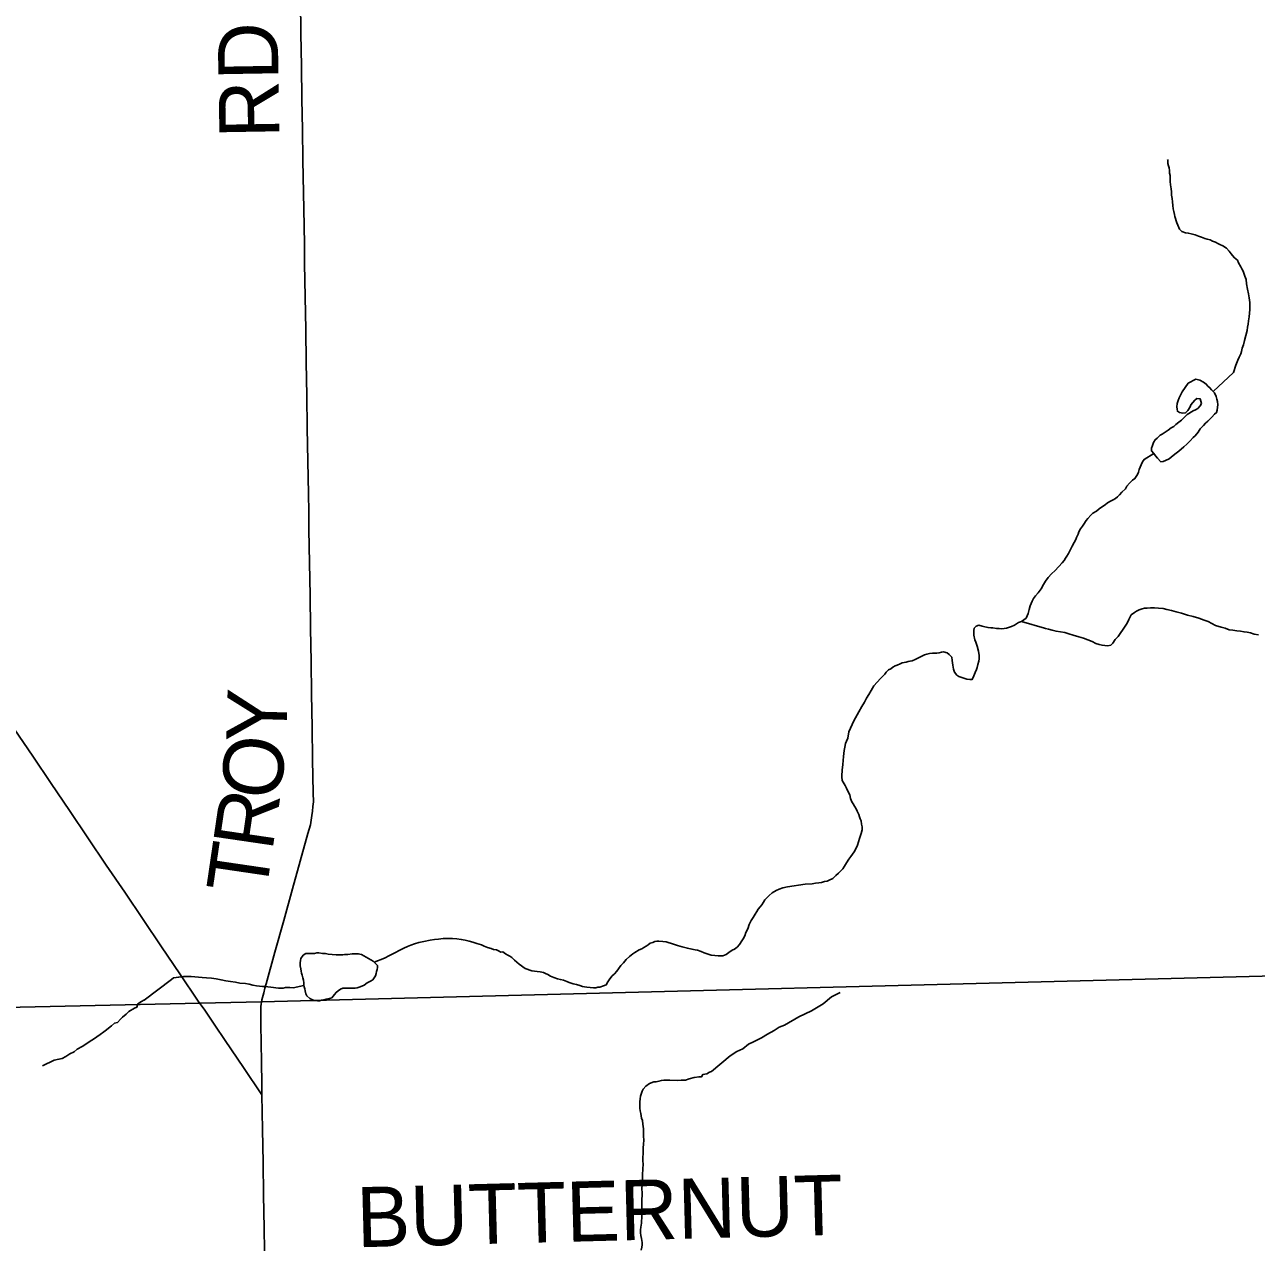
# Model space of a CAD drawing. Extents: x 103424 to 290657, y 38711 to 110967.
# Drawn here: x 160405 to 166595, y 70687 to 76839 of the extents above; entities that cross this region are included whole.
import ezdxf

# ---------------------------------------------------------------- set-up
doc = ezdxf.new("R2010")
doc.units = 0
for name, color, linetype in [('GM_X_Corporation', 7, 'Continuous'), ('GM_X_County_Road', 7, 'Continuous'), ('GM_X_County_Road_Text', 7, 'Continuous'), ('GM_X_Minor_Lake', 7, 'Continuous'), ('GM_X_Minor_River', 7, 'Continuous')]:
    doc.layers.add(name, color=color, linetype=linetype)

msp = doc.modelspace()

# ---------------------------------------------------------------- linework, layer by layer
at = {"layer": 'GM_X_Corporation'}
for points in [[(148594.2, 97294.7), (158050.5, 97608.1), (158064.2, 97608.5), (162306.4, 97749.1), (162479.3, 97753.8), (165116.9, 97825.6), (173478.4, 98058.2), (173550.7, 94746.5), (173649.8, 90059.6), (173693.6, 87690.3), (173775.2, 84514.7), (174054.1, 73155.3), (174066.9, 72315.5), (174070.5, 72208.9), (173777.3, 72202), (169136.7, 72130.4), (166950.9, 72068.3), (161596.3, 71930.5), (161287.7, 71923.7), (157064.3, 71829.7), (151578, 71707.7), (149073.5, 71652)], [(149073.5, 71652), (151578, 71707.7), (157064.3, 71829.7), (161287.7, 71923.7), (161596.3, 71930.5), (166950.9, 72068.3), (169136.7, 72130.4), (173777.3, 72202), (174070.5, 72208.9), (174125.3, 69464.1), (174128.9, 69223), (174137.2, 68978.3), (174140.8, 68790.7), (174153.5, 68330.8), (174162.2, 67903.5), (174163.3, 67850.7), (174375.3, 58453.3)]]:
    msp.add_lwpolyline(points, dxfattribs=at)
at = {"layer": 'GM_X_County_Road'}
for points in [[(161598, 71940.8), (161606.6, 71976.5), (161612.9, 71998.8), (161619, 72020.9), (161663.3, 72180), (161707.6, 72339), (161751.8, 72498), (161790.5, 72636.7), (161829.1, 72775.4), (161835.2, 72797.6), (161841.5, 72819.9), (161844.5, 72842.9), (161848.3, 72865.7), (161851.1, 72888.5), (161853.3, 72911.5), (161856.1, 72934.5), (161855.4, 72980.7), (161852.7, 73145.7), (161850.1, 73310.7), (161847.5, 73475.8), (161844.8, 73640.8), (161842.2, 73805.8), (161839.5, 73970.8), (161836.8, 74135.9), (161834.2, 74300.9), (161832.7, 74391.4), (161831.3, 74481.8), (161828.6, 74646.9), (161825.9, 74811.9), (161823.2, 74976.9), (161820.5, 75142), (161817.8, 75307), (161815.1, 75472), (161812.4, 75637), (161810.9, 75732.9), (161809.3, 75828.8), (161806.7, 75993.8), (161804, 76158.8), (161801.5, 76311.6), (161799.1, 76464.4), (161796.4, 76629.4), (161793.7, 76794.4), (161791, 76959.5)], [(161278.1, 71933.9), (161185.7, 72070.6), (161093.2, 72207.4), (161000.7, 72344.1), (160908.2, 72480.8), (160815.8, 72617.6), (160723.3, 72754.3), (160630.8, 72891.1), (160538.4, 73027.8), (160445.9, 73164.5), (160353.4, 73301.3)], [(161598.1, 71463.9), (161505.5, 71600.5), (161413, 71737.2), (161361.5, 71813.3), (161310.1, 71889.2), (161278.1, 71933.9)], [(161597.2, 71517.1), (161595.4, 71628.9), (161594, 71722.5), (161592.5, 71816.1), (161591.7, 71862.2), (161592.9, 71906.9), (161598, 71940.8)], [(161610.4, 70679.4), (161608.5, 70794.4), (161605.9, 70959.4), (161603.4, 71124.4), (161600.8, 71289.5), (161599.4, 71376.7), (161598.1, 71463.9), (161597.2, 71517.1)]]:
    msp.add_lwpolyline(points, dxfattribs=at)
at = {"layer": 'GM_X_Minor_Lake'}
for points in [[(166071.9, 74725.2), (166068.1, 74711), (166068.3, 74698.8), (166078.7, 74684.9), (166087, 74672.9), (166097.3, 74661), (166113.7, 74643.1), (166125.8, 74645.3), (166137.8, 74649.6), (166155.8, 74658), (166165.8, 74666.2), (166175.7, 74674.5), (166191.6, 74686.9), (166205.6, 74697.2), (166229.4, 74717.9), (166245.3, 74732.3), (166261.2, 74748.7), (166277, 74765.2), (166286.9, 74773.4), (166302.8, 74791.9), (166312.5, 74808.2), (166328.4, 74824.7), (166338.3, 74837), (166350.2, 74847.3), (166360.1, 74857.6), (166370, 74867.9), (166383.9, 74882.3), (166393.8, 74890.5), (166397.6, 74902.7), (166399.4, 74916.9), (166401.2, 74929), (166398.9, 74945.1), (166396.7, 74957.2), (166392.4, 74971.3), (166384, 74989.3), (166369.6, 75005.2), (166361.3, 75015.2), (166351.1, 75023.1), (166342.8, 75033), (166328.5, 75042.9), (166310.2, 75052.6), (166289.9, 75058.3)], [(166289.9, 75058.3), (166310.2, 75052.6), (166328.5, 75042.9), (166342.8, 75033), (166351.1, 75023.1), (166361.3, 75015.2), (166369.6, 75005.2), (166384, 74989.3), (166392.4, 74971.3), (166396.7, 74957.2), (166398.9, 74945.1), (166401.2, 74929), (166399.4, 74916.9), (166397.6, 74902.7), (166393.8, 74890.5), (166383.9, 74882.3), (166370, 74867.9), (166360.1, 74857.6), (166350.2, 74847.3), (166338.3, 74837), (166328.4, 74824.7), (166312.5, 74808.2), (166302.8, 74791.9), (166286.9, 74773.4), (166277, 74765.2), (166261.2, 74748.7), (166245.3, 74732.3), (166229.4, 74717.9), (166205.6, 74697.2), (166191.6, 74686.9), (166175.7, 74674.5), (166165.8, 74666.2), (166155.8, 74658), (166137.8, 74649.6), (166125.8, 74645.3), (166113.7, 74643.1), (166097.3, 74661), (166087, 74672.9), (166078.7, 74684.9), (166068.3, 74698.8), (166068.1, 74711), (166071.9, 74725.2), (166077.7, 74739.4), (166085.5, 74753.7), (166095.5, 74761.9), (166111.3, 74776.4), (166121.3, 74782.6), (166131.3, 74788.8), (166141.3, 74795.1), (166151.2, 74801.3), (166167.2, 74813.7), (166179.2, 74820), (166189.1, 74830.3), (166205, 74842.7), (166218.9, 74853), (166234.8, 74869.5), (166246.7, 74879.8), (166276.6, 74898.5), (166288.6, 74904.8), (166300.6, 74911.1), (166312.5, 74923.4), (166318.4, 74935.6), (166316.1, 74947.7), (166311.9, 74959.8), (166295.7, 74961.5), (166285.7, 74953.2), (166275.9, 74940.9), (166266, 74928.6), (166262.2, 74918.5), (166250.4, 74900.1), (166238.5, 74889.7), (166224.4, 74887.5), (166208.2, 74891.2), (166198, 74897.1), (166195.8, 74907.2), (166195.5, 74919.3), (166197.3, 74935.5), (166201, 74951.7), (166206.9, 74963.9), (166212.7, 74978.2), (166222.5, 74994.5), (166251.9, 75037.5), (166289.9, 75058.3)], [(166289.9, 75058.3), (166251.9, 75037.5), (166222.5, 74994.5), (166212.7, 74978.2), (166206.9, 74963.9), (166201, 74951.7), (166197.3, 74935.5), (166195.5, 74919.3), (166195.8, 74907.2), (166198, 74897.1), (166208.2, 74891.2), (166224.4, 74887.5), (166238.5, 74889.7), (166250.4, 74900.1), (166262.2, 74918.5), (166266, 74928.6), (166275.9, 74940.9), (166285.7, 74953.2), (166295.7, 74961.5), (166311.9, 74959.8), (166316.1, 74947.7), (166318.4, 74935.6), (166312.5, 74923.4), (166300.6, 74911.1), (166288.6, 74904.8), (166276.6, 74898.5), (166246.7, 74879.8), (166234.8, 74869.5), (166218.9, 74853), (166205, 74842.7), (166189.1, 74830.3), (166179.2, 74820), (166167.2, 74813.7), (166151.2, 74801.3), (166141.3, 74795.1), (166131.3, 74788.8), (166121.3, 74782.6), (166111.3, 74776.4), (166095.5, 74761.9), (166085.5, 74753.7), (166077.7, 74739.4), (166071.9, 74725.2)], [(162157.1, 72135.1), (162098.2, 72168.2), (162081.9, 72171.9), (162063.8, 72171.6), (162051.7, 72171.4), (162029.5, 72169), (162013.4, 72168.7), (162003.3, 72166.5), (161991.2, 72166.3), (161971.1, 72165.9), (161950.9, 72167.6), (161930.7, 72169.2), (161916.5, 72173), (161902.3, 72172.8), (161884.1, 72176.5), (161874, 72176.3), (161862, 72174.1), (161845.8, 72173.8), (161831.7, 72173.5), (161817.6, 72173.3), (161805.6, 72165), (161793.8, 72148.6), (161792, 72138.5), (161790.2, 72126.3), (161790.4, 72112.2), (161792.7, 72096.1), (161795, 72084), (161797.2, 72073.9), (161799.4, 72063.9), (161803.6, 72051.8), (161805.9, 72039.7), (161808.1, 72025.6), (161808.3, 72015.5), (161810.5, 72005.5), (161812.7, 71995.4)], [(162157.1, 72135.1), (162098.2, 72168.2), (162081.9, 72171.9), (162063.8, 72171.6), (162051.7, 72171.4), (162029.5, 72169), (162013.4, 72168.7), (162003.3, 72166.5), (161991.2, 72166.3), (161971.1, 72165.9), (161950.9, 72167.6), (161930.7, 72169.2), (161916.5, 72173), (161902.3, 72172.8), (161884.1, 72176.5), (161874, 72176.3), (161862, 72174.1), (161845.8, 72173.8), (161831.7, 72173.5), (161817.6, 72173.3), (161805.6, 72165), (161793.8, 72148.6), (161792, 72138.5), (161790.2, 72126.3), (161790.4, 72112.2), (161792.7, 72096.1), (161795, 72084), (161797.2, 72073.9), (161799.4, 72063.9), (161803.6, 72051.8), (161805.9, 72039.7), (161808.1, 72025.6), (161808.3, 72015.5), (161810.5, 72005.5), (161812.7, 71995.4), (161814.9, 71985.4), (161819.2, 71971.3), (161823.4, 71961.3), (161837.8, 71947.4), (161848, 71941.5), (161860.1, 71937.7), (161876.3, 71935.9), (161886.4, 71936.1), (161896.4, 71938.3), (161908.5, 71940.6), (161920.5, 71944.8), (161936.6, 71947.1), (161948.7, 71951.4), (161962.5, 71967.8), (161970.4, 71978), (161980.3, 71986.3), (161992.3, 71994.6), (162004.3, 71998.8), (162022.5, 71999.2), (162036.6, 71999.4), (162048.7, 71999.6), (162066.9, 72000), (162076.9, 72000.1), (162091, 72006.5), (162111, 72014.9), (162126.9, 72025.3), (162142.9, 72033.7), (162154.9, 72041.9), (162168.7, 72060.4), (162172.5, 72072.6), (162174.3, 72082.7), (162176.2, 72092.8), (162178, 72103), (162177.8, 72113.1), (162157.1, 72135.1)], [(161812.7, 71995.4), (161814.9, 71985.4), (161819.2, 71971.3), (161823.4, 71961.3), (161837.8, 71947.4), (161848, 71941.5), (161860.1, 71937.7), (161876.3, 71935.9), (161886.4, 71936.1), (161896.4, 71938.3), (161908.5, 71940.6), (161920.5, 71944.8), (161936.6, 71947.1), (161948.7, 71951.4), (161962.5, 71967.8), (161970.4, 71978), (161980.3, 71986.3), (161992.3, 71994.6), (162004.3, 71998.8), (162022.5, 71999.2), (162036.6, 71999.4), (162048.7, 71999.6), (162066.9, 72000), (162076.9, 72000.1), (162091, 72006.5), (162111, 72014.9), (162126.9, 72025.3), (162142.9, 72033.7), (162154.9, 72041.9), (162168.7, 72060.4), (162172.5, 72072.6), (162174.3, 72082.7), (162176.2, 72092.8), (162178, 72103), (162177.8, 72113.1), (162157.1, 72135.1)]]:
    msp.add_lwpolyline(points, dxfattribs=at)
at = {"layer": 'GM_X_Minor_River'}
for points in [[(166378.3, 74995.6), (166479.1, 75091), (166490.6, 75127.6), (166502.2, 75154.1), (166508, 75168.3), (166515.8, 75184.6), (166519.6, 75196.8), (166523.3, 75213), (166529.1, 75231.3), (166534.8, 75251.6), (166548, 75302.4), (166549.7, 75318.6), (166553.4, 75334.8), (166555.2, 75351), (166558.8, 75371.3), (166560.5, 75389.5), (166562.2, 75407.7), (166561.9, 75423.8), (166561.6, 75444), (166559.2, 75466.2), (166554.8, 75486.3), (166550.3, 75510.5), (166545.8, 75536.7), (166543.4, 75558.9), (166537, 75574.9), (166528.5, 75601), (166522.2, 75613), (166516, 75623), (166505.6, 75643), (166499.3, 75655), (166482.9, 75668.9), (166468.5, 75686.8), (166458.1, 75700.8), (166443.7, 75716.7), (166425.3, 75728.5), (166411.1, 75734.3), (166400.9, 75740.1), (166388.7, 75746), (166374.5, 75751.8), (166362.3, 75757.6), (166348.1, 75761.4), (166335.9, 75765.2), (166319.6, 75771), (166303.4, 75776.8), (166287.1, 75782.5), (166266.9, 75788.2), (166252.7, 75792), (166238.5, 75793.8), (166220.3, 75799.5), (166207.9, 75811.4), (166199.5, 75831.5), (166195.3, 75843.5), (166184.6, 75875.7), (166182.4, 75885.7), (166180.1, 75899.8), (166175.8, 75913.9), (166175.6, 75930), (166173.2, 75948.2), (166170.9, 75966.3), (166168.6, 75982.4), (166168.3, 75998.6), (166166, 76014.7), (166163.6, 76034.9), (166161.3, 76051), (166161, 76067.1), (166160.7, 76081.3), (166158.5, 76093.4), (166158.3, 76105.5), (166156, 76119.6), (166153.8, 76129.7), (166149.6, 76141.7), (166149.3, 76157.9), (166147.2, 76161.9)], [(165747.6, 74358.8), (165763.4, 74375.2), (165773.4, 74385.5), (165791.3, 74395.9), (165805.3, 74406.3), (165821.2, 74418.7), (165835.2, 74427), (165847.1, 74437.3), (165861.1, 74445.6), (165875.1, 74451.9), (165887.1, 74458.2), (165897, 74466.5), (165906.9, 74476.8), (165918.8, 74491.1), (165936.6, 74507.6), (165944.5, 74519.9), (165956.3, 74536.2), (165972.2, 74550.7), (165984.2, 74559), (165997.9, 74579.4), (166001.7, 74591.6), (166005.6, 74603.8), (166011.4, 74616), (166015.2, 74628.2), (166023, 74642.5), (166030.9, 74654.7), (166079.3, 74684)], [(164746.2, 73597.4), (164758.2, 73603.7), (164768.2, 73611.9), (164780.2, 73618.2), (164790.2, 73622.4), (164804.2, 73628.8), (164814.2, 73633), (164824.3, 73635.2), (164834.3, 73637.4), (164844.4, 73639.6), (164854.4, 73641.8), (164864.5, 73644), (164880.5, 73650.3), (164926.5, 73673.4), (164938.5, 73677.6), (164952.6, 73679.9), (164966.7, 73682.2), (164976.8, 73682.3), (164988.9, 73682.6), (165001, 73682.8), (165013, 73687), (165023.1, 73689.2), (165041.3, 73683.5), (165051.6, 73675.6), (165063.9, 73661.7), (165066.2, 73645.6), (165068.7, 73621.4), (165073.1, 73601.2), (165077.3, 73587.2), (165089.7, 73571.2), (165099.9, 73565.3), (165120.3, 73557.6), (165140.5, 73551.9), (165154.7, 73550.2), (165166.8, 73550.4), (165174.5, 73568.7), (165182.3, 73585), (165188.1, 73599.3), (165192, 73609.4), (165195.7, 73625.7), (165199.5, 73641.9), (165201.3, 73654), (165201, 73670.2), (165198.6, 73692.4), (165192.1, 73716.5), (165185.7, 73736.6), (165179.4, 73748.6), (165174.9, 73772.8), (165174.5, 73795), (165176.3, 73807.1), (165186.2, 73817.4), (165200.3, 73821.7), (165216.5, 73817.9), (165230.7, 73814.2), (165246.9, 73810.4), (165261.1, 73808.6), (165271.1, 73808.8), (165289.4, 73805.1), (165301.5, 73805.3), (165313.6, 73803.5), (165327.7, 73805.8), (165339.8, 73808), (165349.8, 73810.2), (165363.8, 73816.5), (165379.8, 73822.9), (165389.8, 73829.1), (165399.8, 73835.4), (165413.8, 73841.7), (165425.8, 73850), (165437.7, 73858.3), (165447.4, 73880.7), (165453.1, 73901), (165458.8, 73919.3), (165462.7, 73931.4), (165468.5, 73943.7), (165474.3, 73955.9), (165484.2, 73970.2), (165498, 73984.6), (165513.8, 74005.1), (165525.5, 74027.5), (165535.3, 74043.9), (165549.1, 74062.3), (165564.9, 74080.7), (165582.8, 74097.2), (165618.4, 74136.2), (165628.3, 74146.5), (165636.2, 74158.8), (165642, 74169), (165649.9, 74183.3), (165659.7, 74199.6), (165669.4, 74220), (165679.1, 74238.4), (165686.9, 74252.6), (165690.8, 74262.8), (165698.6, 74279.1), (165702.4, 74291.3), (165710.2, 74305.6), (165720.1, 74319.9), (165727.9, 74330.1), (165739.7, 74348.5), (165747.6, 74358.8)], [(165413.8, 73841.7), (165529.4, 73807.4), (165535.5, 73805.5), (165549.7, 73801.7), (165567.9, 73798), (165588.2, 73792.3), (165610.5, 73788.6), (165632.8, 73785), (165653, 73779.3), (165673.4, 73771.6), (165701.7, 73764), (165726.1, 73756.4), (165748.4, 73748.7), (165768.7, 73741), (165787.1, 73731.2), (165805.3, 73725.5), (165819.5, 73721.7), (165833.7, 73719.9), (165847.8, 73718.1), (165863.9, 73722.5), (165873.8, 73732.7), (165885.6, 73751.1), (165899.5, 73765.5), (165934.9, 73816.7), (165944.7, 73833), (165954.4, 73851.4), (165966.1, 73873.8), (165982.1, 73886.2), (165992, 73892.4), (166006, 73898.7), (166020.1, 73905.1), (166032.1, 73907.3), (166046.2, 73907.5), (166062.3, 73909.9), (166082.5, 73910.2), (166102.7, 73908.5), (166127, 73907), (166145.2, 73901.2), (166167.5, 73895.6), (166191.8, 73889.9), (166218.2, 73882.3), (166248.6, 73872.8), (166277, 73865.2), (166305.4, 73857.6), (166331.8, 73848), (166352.1, 73840.3), (166370.5, 73830.5), (166388.8, 73820.8), (166417.2, 73813.2), (166437.5, 73807.5), (166457.8, 73799.8), (166476, 73798.1), (166496.2, 73794.4), (166514.4, 73792.7), (166532.6, 73789), (166548.8, 73787.3), (166565, 73783.5), (166583.3, 73777.8), (166605.6, 73774.1)], [(163873.9, 72163.6), (163890.1, 72161.9), (163902.2, 72162.1), (163914.3, 72162.3), (163930.3, 72168.7), (163944.3, 72179), (163960.2, 72189.4), (163972.2, 72195.7), (163986.2, 72206), (163998.1, 72218.4), (164009.8, 72236.8), (164015.7, 72247), (164023.5, 72261.3), (164029.2, 72279.5), (164039, 72297.9), (164046.7, 72318.2), (164056.4, 72338.6), (164066.2, 72354.9), (164076, 72371.3), (164083.9, 72383.6), (164091.7, 72395.8), (164101.6, 72408.1), (164109.5, 72418.3), (164117.4, 72430.6), (164125.2, 72442.9), (164137.1, 72455.2), (164147, 72465.5), (164160.9, 72477.8), (164180.9, 72490.3), (164196.9, 72496.7), (164214.9, 72503.1), (164239.1, 72507.5), (164327.6, 72521.2), (164361.9, 72523.9), (164380, 72526.2), (164396.1, 72528.5), (164410.2, 72530.8), (164424.2, 72535.1), (164438.3, 72537.4), (164448.3, 72541.6), (164466.3, 72550), (164482.2, 72564.4), (164494.1, 72576.7), (164506, 72589.1), (164515.9, 72599.3), (164525.8, 72611.7), (164535.5, 72628), (164547.3, 72646.4), (164557.2, 72660.7), (164572.9, 72683.2), (164582.7, 72699.5), (164590.4, 72717.9), (164599.9, 72750.3), (164609.6, 72776.8), (164613.3, 72795), (164613, 72809.2), (164610.8, 72823.3), (164608.4, 72839.4), (164604.2, 72849.4), (164600, 72859.4), (164597.8, 72871.5), (164589.4, 72887.5), (164583.2, 72899.5), (164574.8, 72913.5), (164568.6, 72925.5), (164562.3, 72935.5), (164556, 72951.6), (164551.6, 72969.7), (164543.3, 72985.7), (164534.9, 73003.7), (164528.6, 73017.8), (164514, 73041.7), (164511.7, 73059.9), (164511.4, 73074), (164513.2, 73086.2), (164513.1, 73096.3), (164514.9, 73108.4), (164516.6, 73122.6), (164518.3, 73142.8), (164519.9, 73163.1), (164521.7, 73177.2), (164523.4, 73193.4), (164527.2, 73209.6), (164530.9, 73227.9), (164534.7, 73240.1), (164542.5, 73254.4), (164546, 73286.8), (164571.2, 73341.8), (164596.7, 73386.6), (164612.3, 73413.2), (164626, 73435.7), (164635.8, 73456), (164647.5, 73474.4), (164659.3, 73494.8), (164673, 73517.3), (164688.8, 73535.8), (164706.6, 73554.3), (164716.6, 73564.6), (164728.4, 73576.9), (164734.3, 73587.1), (164746.2, 73597.4)], [(162162.5, 72129.3), (162213.5, 72150.1), (162239.5, 72162.7), (162265.5, 72177.3), (162291.5, 72189.8), (162311.5, 72200.3), (162329.5, 72208.7), (162345.5, 72215.1), (162363.6, 72221.4), (162385.6, 72227.9), (162411.8, 72234.4), (162443.9, 72241.1), (162464.1, 72243.4), (162484.2, 72245.8), (162508.4, 72248.3), (162532.6, 72248.7), (162554.8, 72249.1), (162577, 72247.5), (162599.3, 72243.8), (162619.5, 72240.2), (162639.8, 72234.5), (162658, 72230.8), (162678.3, 72223), (162700.6, 72217.4), (162714.9, 72209.5), (162731.1, 72203.8), (162749.4, 72198), (162761.6, 72194.2), (162775.7, 72192.5), (162785.9, 72186.6), (162798.1, 72180.7), (162808.2, 72180.9), (162822.5, 72171.1), (162832.7, 72165.2), (162842.9, 72159.3), (162853.1, 72153.4), (162867.5, 72139.5), (162890, 72119.8), (162920.7, 72098.1), (162953.2, 72086.5), (162981.5, 72083), (162995.6, 72081.2), (163011.8, 72077.5), (163022, 72073.6), (163034.2, 72067.8), (163048.5, 72060), (163064.8, 72052.2), (163083, 72046.4), (163097.2, 72042.6), (163113.4, 72038.9), (163129.7, 72033.1), (163141.9, 72027.3), (163162.2, 72021.6), (163178.4, 72017.8), (163194.6, 72012.1), (163208.8, 72008.3), (163218.9, 72006.5), (163231.1, 72004.6), (163263.4, 72001.2), (163275.5, 72001.4), (163285.6, 72003.6), (163295.6, 72003.8), (163313.7, 72010.2), (163327.7, 72016.5), (163335.5, 72030.8), (163343.4, 72041), (163355.2, 72059.4), (163369.1, 72071.8), (163381, 72084.1), (163388.8, 72096.4), (163400.7, 72112.7), (163414.5, 72127.1), (163428.4, 72143.5), (163444.2, 72158), (163462.1, 72172.4), (163472.1, 72178.6), (163494.1, 72191.2), (163506.1, 72197.4), (163516.1, 72203.7), (163528.1, 72210), (163538, 72216.2), (163548, 72224.5), (163562, 72228.8), (163572, 72233), (163582.1, 72235.2), (163592.2, 72235.4), (163612.4, 72233.7), (163628.6, 72232), (163665.1, 72220.5), (163685.4, 72212.8), (163709.7, 72207.1), (163736.1, 72199.5), (163758.3, 72195.9), (163774.5, 72192.2), (163786.7, 72190.3), (163805, 72182.6), (163819.2, 72176.8), (163835.5, 72171), (163855.7, 72165.3), (163873.9, 72163.6)], [(160495.2, 71609.6), (160553.9, 71637.5), (160578, 71642), (160594.1, 71646.3), (160612.1, 71656.8), (160632, 71669.2), (160654, 71679.7), (160670, 71692.1), (160693.9, 71706.7), (160743.8, 71737.9), (160755.8, 71746.2), (160767.7, 71754.5), (160785.7, 71766.9), (160803.6, 71779.4), (160817.5, 71789.7), (160827.5, 71798), (160841.4, 71810.3), (160857.3, 71822.8), (160871.4, 71827.1), (160887.2, 71843.5), (160897.1, 71853.8), (160915, 71868.2), (160928.9, 71882.6), (160956.8, 71899.3), (160968.9, 71903.5), (160974.6, 71919.8), (160992.6, 71932.3), (161004.6, 71938.5), (161006.6, 71938.6), (161144, 72042)], [(161144, 72042), (161153.9, 72050.3), (161180, 72054.8), (161204.2, 72057.2), (161220.4, 72057.5), (161242.5, 72057.9), (161260.7, 72056.2), (161278.9, 72054.6), (161297.1, 72052.9), (161319.3, 72051.2), (161343.6, 72049.6), (161367.9, 72046), (161392.2, 72040.4), (161416.4, 72036.8), (161440.7, 72033.2), (161465, 72029.6), (161487.3, 72023.9), (161515.6, 72022.4), (161533.8, 72018.7), (161552, 72015), (161570.3, 72011.3), (161586.4, 72009.5), (161600.6, 72007.8), (161614.7, 72008), (161655.2, 72002.7), (161667.3, 72000.9), (161681.5, 71999.1), (161691.6, 71999.3), (161703.7, 71999.5), (161715.7, 72001.8), (161725.8, 72001.9), (161737.9, 72002.2), (161754.1, 72000.4), (161809.1, 72011.9)], [(164502.8, 71978.2), (164460.5, 71955.7), (164418.3, 71921.2), (164360, 71884.6), (164295.7, 71856), (164223.3, 71813.2), (164197.1, 71803), (164171, 71786.7), (164138.8, 71768.4), (164108.6, 71750), (164068.4, 71729.6), (164042.3, 71717.4), (164014.1, 71695.1), (163984, 71680.8), (163951.1, 71659)], [(163506.3, 70942.4), (163508.1, 70954.6), (163507.7, 70972.7), (163507.4, 70988.9), (163510.3, 71041.4), (163510, 71055.6), (163509.7, 71069.7), (163511.4, 71083.9), (163511.2, 71094), (163512.8, 71114.2), (163512.3, 71134.4), (163512, 71152.5), (163513.7, 71164.7), (163513.4, 71180.8), (163513, 71197), (163514.7, 71215.2), (163516.3, 71235.4), (163515.8, 71255.6), (163515.4, 71273.8), (163515.1, 71291.9), (163512.5, 71316.1), (163510.1, 71334.2), (163505.8, 71346.2), (163503.5, 71358.3), (163501.3, 71370.4), (163499, 71382.4), (163496.7, 71396.5), (163496.3, 71412.7), (163496, 71428.8), (163497.7, 71443), (163499.4, 71457.1), (163503.2, 71467.3), (163509, 71481.6), (163512.8, 71491.8), (163526.7, 71506.2), (163544.5, 71520.7), (163566.6, 71529.3), (163578.7, 71529.5), (163592.8, 71531.9), (163604.9, 71536.2), (163617, 71536.4), (163631.1, 71536.7), (163647.3, 71537.1), (163683.7, 71535.9), (163703.9, 71536.3), (163726.1, 71536.8), (163744.2, 71543.2), (163770.3, 71549.8), (163794.5, 71554.4), (163806.6, 71554.7), (163812.4, 71564.9), (163832.5, 71569.4), (163846.5, 71577.7), (163856.6, 71580), (163951.1, 71659), (163856.6, 71580)], [(163503.7, 70683.9), (163507.5, 70698.1), (163509.2, 70710.3), (163509, 70722.4), (163506.7, 70732.4), (163504.5, 70742.5), (163502.2, 70756.6), (163499.9, 70770.7), (163499.6, 70784.8), (163501.3, 70798.9), (163504.9, 70819.2), (163504.6, 70831.3), (163506.4, 70843.5), (163506.2, 70853.6), (163508, 70865.7), (163507.7, 70879.8), (163507.4, 70894), (163507, 70910.1), (163506.7, 70926.3), (163506.3, 70942.4)]]:
    msp.add_lwpolyline(points, dxfattribs=at)

# ---------------------------------------------------------------- texts
at = {"layer": 'GM_X_County_Road_Text'}
for s, height, rotation, p in [('RD', 301.87, 90.98725, (161686.5, 76270.2)), ('Y', 301.9, 88.38797, (161720, 73231)), ('O', 301.9, 83.3066, (161687, 72938)), ('R', 301.9, 81.64719, (161649.7, 72683.2)), ('T', 301.9, 81.64321, (161616.9, 72459.8)), ('BUTTERNUT', 301.87, 1.5012, (162076.9, 70697.4))]:
    msp.add_text(s, height=height, rotation=rotation, dxfattribs=at).set_placement(p)

doc.saveas('drawing.dxf')
